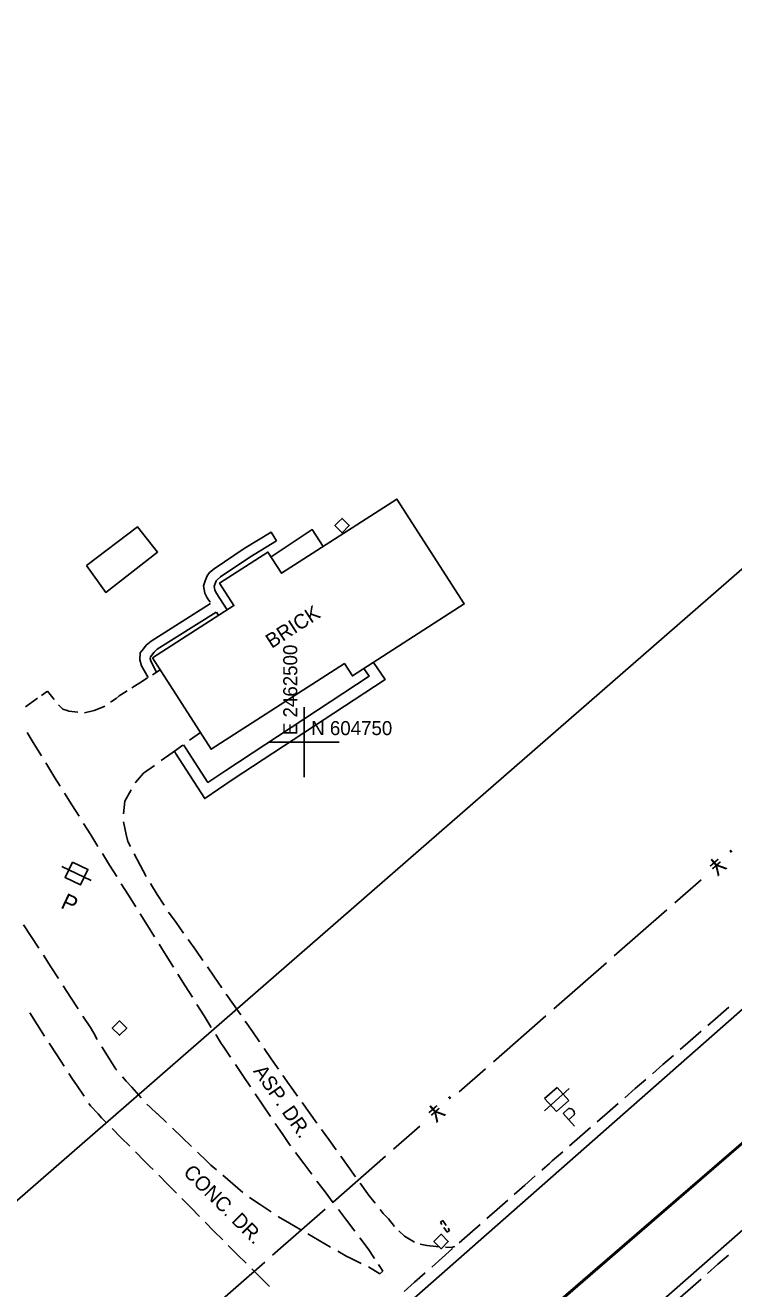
# Model space of a CAD drawing. Extents: x 2443269 to 2494951, y 591171 to 622130.
# Drawn here: x 2462420.2 to 2462622.9, y 604593.6 to 604955.1 of the extents above; entities that cross this region are included whole.
import ezdxf

# ---------------------------------------------------------------- set-up
doc = ezdxf.new("R2010")
doc.units = 0
for name, color, linetype in [('SURVEY - CONTROL - Grid', 7, 'Continuous'), ('SURVEY - CONTROL - Grid Text', 7, 'Continuous'), ('SURVEY - DRAINAGE - Area Shapes', 7, 'Continuous'), ('SURVEY - DRAINAGE - Bridges', 7, 'Continuous'), ('SURVEY - NON-TRANSPORTATION - Buildings', 7, 'Continuous'), ('SURVEY - NON-TRANSPORTATION - Buildings Text', 7, 'Continuous'), ('SURVEY - NON-TRANSPORTATION - Features', 7, 'Continuous'), ('SURVEY - PROPERTY - ROW Lines', 7, 'Continuous'), ('SURVEY - TRANSPORTATION - Features', 7, 'Continuous'), ('SURVEY - TRANSPORTATION - Features Text', 7, 'Continuous'), ('SURVEY - TRANSPORTATION - Roads', 7, 'Continuous'), ('SURVEY - UTILITIES - Cable (Underground) with Text', 7, 'Continuous'), ('SURVEY - UTILITIES - Poles and Miscellaneous with Text', 7, 'Continuous'), ('SURVEY - UTILITIES - Sanitary Sewer with Text', 7, 'Continuous')]:
    doc.layers.add(name, color=color, linetype=linetype)

# ---------------------------------------------------------------- blocks, each defined once
blk = doc.blocks.new('xpp')
at = {"layer": 'SURVEY - UTILITIES - Cable (Underground) with Text'}
for p, q in [((-4.75, 0), (4.75, 0)), ((-2.395, 2.598), (2.395, 2.598)), ((-2.395, -2.436), (-2.395, 2.598)), ((2.395, 2.598), (2.395, 2.598)), ((2.395, 2.598), (2.395, -2.436)), ((2.395, -2.436), (-2.395, -2.436)), ((-2.395, -2.436), (-2.395, -2.436)), ((2.395, -2.436), (2.395, -2.436)), ((-1.339, -8.932), (-1.339, -4.141)), ((-1.339, -4.141), (-1.339, -4.141)), ((-1.339, -4.141), (0.771, -4.141)), ((0.771, -6.496), (-1.339, -6.496)), ((1.062, -4.351), (0.771, -4.141)), ((0.771, -6.496), (1.062, -6.285)), ((1.286, -4.632), (1.062, -4.351)), ((1.062, -4.351), (1.062, -4.351)), ((1.062, -6.285), (1.286, -6.004)), ((1.062, -6.285), (1.062, -6.285)), ((1.427, -4.962), (1.286, -4.632)), ((1.286, -4.632), (1.286, -4.632)), ((1.286, -6.004), (1.427, -5.674)), ((1.286, -6.004), (1.286, -6.004)), ((1.475, -5.318), (1.427, -4.962)), ((1.427, -4.962), (1.427, -4.962)), ((1.427, -5.674), (1.475, -5.318)), ((1.427, -5.674), (1.427, -5.674)), ((1.475, -5.318), (1.475, -5.318))]:
    blk.add_line(p, q, dxfattribs=at)

msp = doc.modelspace()

# ---------------------------------------------------------------- linework, layer by layer
at = {"layer": 'SURVEY - CONTROL - Grid'}
for p, q in [((2462500, 604740), (2462500, 604760)), ((2462490, 604750), (2462510, 604750)), ((2462522.915, 604597.393), (2462522.915, 604597.393))]:
    msp.add_line(p, q, dxfattribs=at)
at = {"layer": 'SURVEY - DRAINAGE - Area Shapes'}
for points in [[(2461699.802, 604946.811), (2461948.759, 605058.451), (2462209.695, 605140.681), (2462347.245, 605149.404), (2462473.247, 605118.739), (2462639.239, 604980.206), (2462813.204, 604824.031), (2462826.669, 604809.207), (2462512.785, 604538.294), (2462060.635, 604143.095), (2461848.299, 603959.822)], [(2461699.802, 604946.811), (2461948.759, 605058.451), (2462209.695, 605140.681), (2462347.245, 605149.404), (2462473.247, 605118.739), (2462639.239, 604980.206), (2462813.204, 604824.031), (2462826.669, 604809.207), (2462404.086, 604443.772), (2462278.014, 604331.283), (2462060.635, 604143.095), (2461831.285, 603941.863)]]:
    msp.add_lwpolyline(points, dxfattribs=at)
at = {"layer": 'SURVEY - DRAINAGE - Bridges'}
for p, q in [((2462539.71, 604613.109), (2462538.995, 604612.643)), ((2462538.995, 604612.643), (2462539.418, 604611.993)), ((2462539.71, 604613.109), (2462540.599, 604611.744)), ((2462539.973, 604611.14), (2462540.862, 604609.776)), ((2462541.577, 604610.241), (2462540.862, 604609.776)), ((2462540.862, 604609.776), (2462540.862, 604609.776)), ((2462541.154, 604610.891), (2462541.577, 604610.241))]:
    msp.add_line(p, q, dxfattribs=at)
at = {"layer": 'SURVEY - NON-TRANSPORTATION - Buildings'}
msp.add_lwpolyline([(2462456.574, 604774.07), (2462479.907, 604789.08), (2462475.786, 604795.487), (2462489.615, 604804.381), (2462493.523, 604798.309), (2462526.515, 604819.529), (2462545.809, 604789.532), (2462513.772, 604768.929), (2462511.492, 604772.475), (2462473.368, 604747.958)], close=True, dxfattribs=at)
at = {"layer": 'SURVEY - NON-TRANSPORTATION - Features'}
msp.add_line((2462475.485, 604786.235), (2462474.881, 604787.18), dxfattribs=at)
for points in [[(2462509.807, 604812.984), (2462510.838, 604814.015), (2462512.9, 604811.953), (2462510.838, 604809.89), (2462508.775, 604811.953)], [(2462437.696, 604800.484), (2462452.25, 604811.626), (2462458.057, 604804.349), (2462443.214, 604792.833)], [(2462446.122, 604669.211), (2462447.154, 604670.242), (2462449.216, 604668.18), (2462447.154, 604666.118), (2462445.091, 604668.18)], [(2462538.143, 604608.148), (2462539.174, 604609.179), (2462541.237, 604607.117), (2462539.174, 604605.055), (2462537.112, 604607.117)]]:
    msp.add_lwpolyline(points, close=True, dxfattribs=at)
for points in [[(2462473.076, 604789.995), (2462472.253, 604791.284), (2462471.603, 604792.62), (2462471.151, 604794.713), (2462471.643, 604796.13), (2462472.227, 604797.551), (2462472.903, 604798.492), (2462474.244, 604799.618), (2462482.857, 604805.412), (2462490.504, 604810.077), (2462492.04, 604807.554)], [(2462505.452, 604805.979), (2462502.286, 604810.802), (2462490.517, 604802.981)], [(2462477.971, 604787.833), (2462474.832, 604792.731), (2462474.415, 604793.591), (2462474.212, 604794.526), (2462474.405, 604795.084), (2462474.825, 604796.11), (2462475.084, 604796.468), (2462476.023, 604797.255), (2462484.451, 604802.925), (2462492.04, 604807.554)], [(2462455.36, 604768.483), (2462453.428, 604771.832), (2462452.972, 604773.548), (2462453.09, 604775.54), (2462454.051, 604776.668), (2462454.822, 604777.705), (2462456.164, 604778.925), (2462473.185, 604789.66)], [(2462457.719, 604769.972), (2462456.187, 604772.948), (2462455.947, 604773.847), (2462455.98, 604774.378), (2462456.361, 604774.828), (2462457.02, 604775.714), (2462457.958, 604776.567), (2462474.76, 604787.164)], [(2462519.812, 604772.813), (2462523.181, 604767.944), (2462479.376, 604739.178), (2462471.531, 604733.85), (2462463.136, 604746.793), (2462462.863, 604747.436)], [(2462517.049, 604771.038), (2462518.572, 604768.84), (2462477.555, 604741.908), (2462472.46, 604738.447), (2462466.013, 604748.384), (2462465.416, 604749.257)]]:
    msp.add_lwpolyline(points, dxfattribs=at)
at = {"layer": 'SURVEY - PROPERTY - ROW Lines'}
msp.add_line((2462832.634, 604980.177), (2461653.501, 603953.054), dxfattribs=at)
at = {"layer": 'SURVEY - TRANSPORTATION - Features'}
for p, q in [((2462456.548, 604769.233), (2462458.779, 604770.641)), ((2462458.779, 604770.641), (2462458.779, 604770.641)), ((2462450.691, 604765.535), (2462452.922, 604766.944)), ((2462452.922, 604766.944), (2462455.153, 604768.352)), ((2462424.818, 604763.355), (2462426.567, 604764.601)), ((2462426.567, 604764.601), (2462426.567, 604764.601)), ((2462426.567, 604764.601), (2462428.472, 604762.169)), ((2462446.203, 604762.495), (2462447.066, 604763.246)), ((2462447.066, 604763.246), (2462449.297, 604764.655)), ((2462447.066, 604763.246), (2462447.066, 604763.246)), ((2462420.224, 604760.082), (2462421.974, 604761.329)), ((2462421.974, 604761.329), (2462423.724, 604762.575)), ((2462429.68, 604760.664), (2462430.974, 604759.431)), ((2462430.974, 604759.431), (2462432.204, 604759.004)), ((2462440.145, 604759.146), (2462442.758, 604760.159)), ((2462442.758, 604760.159), (2462442.993, 604760.325)), ((2462444.567, 604761.444), (2462444.865, 604761.655)), ((2462444.865, 604761.655), (2462446.203, 604762.495)), ((2462432.204, 604759.004), (2462432.676, 604758.84)), ((2462432.676, 604758.84), (2462435.248, 604758.533)), ((2462437.162, 604758.35), (2462439.897, 604759.05)), ((2462439.897, 604759.05), (2462440.145, 604759.146)), ((2462422.745, 604749.399), (2462420.706, 604752.702)), ((2462470.294, 604752.738), (2462467.198, 604750.529)), ((2462424.783, 604746.097), (2462422.745, 604749.399)), ((2462465.264, 604749.149), (2462462.168, 604746.941)), ((2462462.168, 604746.941), (2462459.072, 604744.732)), ((2462428.095, 604740.73), (2462426.057, 604744.032)), ((2462454.041, 604741.143), (2462451.731, 604738.417)), ((2462457.137, 604743.352), (2462454.041, 604741.143)), ((2462454.041, 604741.143), (2462454.041, 604741.143)), ((2462428.67, 604739.798), (2462428.095, 604740.73)), ((2462430.149, 604737.437), (2462428.67, 604739.798)), ((2462451.731, 604738.417), (2462451.67, 604738.313)), ((2462433.497, 604732.092), (2462431.437, 604735.381)), ((2462450.503, 604736.321), (2462448.636, 604733.134)), ((2462435.557, 604728.803), (2462433.497, 604732.092)), ((2462448.634, 604733.132), (2462448.264, 604729.459)), ((2462448.636, 604733.134), (2462448.634, 604733.132)), ((2462438.904, 604723.458), (2462436.844, 604726.747)), ((2462448.249, 604727.176), (2462449.08, 604723.576)), ((2462440.964, 604720.169), (2462438.904, 604723.458)), ((2462449.08, 604723.576), (2462449.55, 604721.54)), ((2462449.55, 604721.54), (2462450.289, 604720.116)), ((2462444.312, 604714.824), (2462442.252, 604718.114)), ((2462451.352, 604718.067), (2462453.054, 604714.788)), ((2462446.372, 604711.535), (2462444.312, 604714.824)), ((2462453.054, 604714.788), (2462454.755, 604711.51)), ((2462449.719, 604706.19), (2462447.659, 604709.48)), ((2462455.972, 604709.549), (2462457.944, 604706.425)), ((2462451.779, 604702.901), (2462449.719, 604706.19)), ((2462457.944, 604706.425), (2462459.915, 604703.301)), ((2462461.176, 604701.368), (2462463.324, 604698.363)), ((2462455.126, 604697.557), (2462453.066, 604700.846)), ((2462463.324, 604698.363), (2462465.472, 604695.358)), ((2462419.715, 604697.677), (2462421.867, 604694.37)), ((2462421.867, 604694.37), (2462424.018, 604691.062)), ((2462457.186, 604694.267), (2462455.126, 604697.557)), ((2462460.534, 604688.923), (2462458.474, 604692.212)), ((2462466.814, 604693.479), (2462468.962, 604690.474)), ((2462425.363, 604688.995), (2462427.514, 604685.687)), ((2462462.594, 604685.634), (2462460.534, 604688.923)), ((2462468.962, 604690.474), (2462468.962, 604690.474)), ((2462468.962, 604690.474), (2462471.02, 604687.514)), ((2462427.514, 604685.687), (2462429.666, 604682.38)), ((2462465.941, 604680.289), (2462463.881, 604683.578)), ((2462472.306, 604685.664), (2462474.364, 604682.704)), ((2462431.011, 604680.312), (2462433.162, 604677.005)), ((2462468.001, 604677), (2462465.941, 604680.289)), ((2462474.364, 604682.704), (2462476.422, 604679.743)), ((2462433.162, 604677.005), (2462435.314, 604673.697)), ((2462477.708, 604677.893), (2462479.766, 604674.933)), ((2462423.6, 604669.212), (2462421.468, 604672.515)), ((2462471.349, 604671.655), (2462469.289, 604674.944)), ((2462479.766, 604674.933), (2462481.824, 604671.973)), ((2462618.484, 604671.527), (2462621.5, 604674.151)), ((2462425.731, 604665.909), (2462423.6, 604669.212)), ((2462436.659, 604671.63), (2462438.81, 604668.323)), ((2462473.409, 604668.366), (2462471.349, 604671.655)), ((2462483.11, 604670.123), (2462485.168, 604667.162)), ((2462615.468, 604668.902), (2462618.484, 604671.527)), ((2462438.81, 604668.323), (2462439.829, 604666.757)), ((2462439.829, 604666.757), (2462440.799, 604664.919)), ((2462476.265, 604663.804), (2462474.696, 604666.31)), ((2462485.168, 604667.162), (2462487.226, 604664.202)), ((2462610.567, 604664.636), (2462613.583, 604667.261)), ((2462429.195, 604660.541), (2462427.063, 604663.844)), ((2462442.089, 604662.819), (2462444.212, 604659.493)), ((2462476.782, 604663.038), (2462476.265, 604663.804)), ((2462478.951, 604659.819), (2462476.782, 604663.038)), ((2462488.513, 604662.352), (2462490.57, 604659.392)), ((2462607.551, 604662.011), (2462610.567, 604664.636)), ((2462431.326, 604657.237), (2462429.195, 604660.541)), ((2462444.212, 604659.493), (2462444.212, 604659.493)), ((2462444.212, 604659.493), (2462446.079, 604656.436)), ((2462490.57, 604659.392), (2462492.628, 604656.432)), ((2462602.65, 604657.746), (2462605.666, 604660.371)), ((2462433.713, 604653.539), (2462432.658, 604655.173)), ((2462446.079, 604656.436), (2462446.351, 604656.122)), ((2462482.475, 604654.59), (2462480.306, 604657.808)), ((2462484.644, 604651.371), (2462482.475, 604654.59)), ((2462493.915, 604654.581), (2462495.698, 604652.016)), ((2462599.634, 604655.121), (2462602.65, 604657.746)), ((2462434.842, 604651.905), (2462433.713, 604653.539)), ((2462437.077, 604648.671), (2462434.842, 604651.905)), ((2462447.991, 604654.237), (2462449.077, 604652.987)), ((2462449.077, 604652.987), (2462450.637, 604651.24)), ((2462450.637, 604651.24), (2462453.298, 604648.257)), ((2462495.698, 604652.016), (2462495.979, 604651.626)), ((2462495.979, 604651.626), (2462498.083, 604648.698)), ((2462591.717, 604648.23), (2462594.733, 604650.855)), ((2462594.733, 604650.855), (2462597.749, 604653.48)), ((2462488.169, 604646.141), (2462486, 604649.36)), ((2462438.851, 604645.891), (2462438.407, 604646.605)), ((2462441.013, 604643.683), (2462438.851, 604645.891)), ((2462441.948, 604642.535), (2462441.013, 604643.683)), ((2462454.969, 604646.399), (2462455.928, 604645.507)), ((2462455.928, 604645.507), (2462457.903, 604643.683)), ((2462457.903, 604643.778), (2462460.616, 604641.174)), ((2462457.903, 604643.683), (2462457.903, 604643.683)), ((2462490.338, 604642.923), (2462488.169, 604646.141)), ((2462499.399, 604646.869), (2462501.504, 604643.942)), ((2462501.504, 604643.942), (2462503.608, 604641.015)), ((2462583.799, 604641.34), (2462586.815, 604643.965)), ((2462586.815, 604643.965), (2462589.831, 604646.59)), ((2462443.428, 604641.025), (2462441.948, 604642.535)), ((2462493.862, 604637.693), (2462491.693, 604640.912)), ((2462447.56, 604636.895), (2462445.016, 604639.436)), ((2462450.104, 604634.355), (2462447.56, 604636.895)), ((2462462.312, 604639.547), (2462465.026, 604636.943)), ((2462465.026, 604636.943), (2462467.74, 604634.339)), ((2462495.793, 604634.828), (2462493.862, 604637.693)), ((2462504.924, 604639.185), (2462507.028, 604636.258)), ((2462575.882, 604634.449), (2462578.898, 604637.074)), ((2462578.898, 604637.074), (2462581.914, 604639.699)), ((2462454.237, 604630.227), (2462451.693, 604632.767)), ((2462469.436, 604632.711), (2462472.15, 604630.107)), ((2462496.049, 604634.488), (2462495.793, 604634.828)), ((2462507.028, 604636.258), (2462509.133, 604633.331)), ((2462570.981, 604630.184), (2462573.997, 604632.809)), ((2462455.849, 604628.617), (2462454.237, 604630.227)), ((2462472.15, 604630.107), (2462473.316, 604628.988)), ((2462499.848, 604629.454), (2462497.51, 604632.552)), ((2462502.186, 604626.356), (2462499.848, 604629.454)), ((2462510.448, 604631.501), (2462512.553, 604628.574)), ((2462567.977, 604627.546), (2462570.173, 604629.48)), ((2462570.173, 604629.48), (2462570.981, 604630.184)), ((2462456.776, 604627.681), (2462455.849, 604628.617)), ((2462460.886, 604623.53), (2462458.357, 604626.085)), ((2462473.316, 604628.988), (2462474.947, 604627.596)), ((2462476.735, 604626.07), (2462479.596, 604623.628)), ((2462512.553, 604628.574), (2462514.658, 604625.647)), ((2462563.101, 604623.251), (2462566.102, 604625.894)), ((2462463.415, 604620.976), (2462460.886, 604623.53)), ((2462479.596, 604623.628), (2462482.457, 604621.187)), ((2462505.984, 604621.322), (2462503.647, 604624.42)), ((2462515.973, 604623.818), (2462518.078, 604620.89)), ((2462560.101, 604620.608), (2462563.101, 604623.251)), ((2462467.526, 604616.825), (2462464.996, 604619.379)), ((2462484.309, 604619.745), (2462487.44, 604617.662)), ((2462508.322, 604618.224), (2462505.984, 604621.322)), ((2462518.078, 604620.89), (2462518.332, 604620.537)), ((2462518.332, 604620.537), (2462520.317, 604618.065)), ((2462555.225, 604616.314), (2462558.226, 604618.956)), ((2462470.055, 604614.27), (2462467.526, 604616.825)), ((2462487.44, 604617.662), (2462490.571, 604615.578)), ((2462512.121, 604613.19), (2462509.783, 604616.288)), ((2462521.728, 604616.308), (2462522.64, 604615.172)), ((2462522.64, 604615.172), (2462523.204, 604614.595)), ((2462523.204, 604614.595), (2462524.143, 604613.637)), ((2462552.225, 604613.671), (2462555.225, 604616.314)), ((2462474.166, 604610.119), (2462471.636, 604612.674)), ((2462492.528, 604614.276), (2462492.689, 604614.169)), ((2462492.689, 604614.169), (2462495.773, 604612.375)), ((2462495.773, 604612.375), (2462499.025, 604610.485)), ((2462514.458, 604610.092), (2462512.121, 604613.19)), ((2462524.143, 604613.637), (2462525.839, 604611.43)), ((2462547.35, 604609.376), (2462550.35, 604612.019)), ((2462476.695, 604607.565), (2462474.166, 604610.119)), ((2462501.057, 604609.303), (2462504.308, 604607.413)), ((2462504.308, 604607.413), (2462507.56, 604605.522)), ((2462518.257, 604605.058), (2462515.919, 604608.156)), ((2462527.05, 604610.189), (2462528.742, 604608.653)), ((2462528.742, 604608.653), (2462529.169, 604608.394)), ((2462529.169, 604608.394), (2462531.546, 604606.946)), ((2462544.349, 604606.733), (2462547.35, 604609.376)), ((2462480.081, 604604.146), (2462478.276, 604605.968)), ((2462480.813, 604603.421), (2462480.081, 604604.146)), ((2462509.592, 604604.341), (2462512.168, 604602.843)), ((2462520.137, 604602.278), (2462518.257, 604605.058)), ((2462518.257, 604605.058), (2462518.257, 604605.058)), ((2462533.155, 604606.364), (2462535.078, 604606.022)), ((2462535.078, 604606.022), (2462535.903, 604605.924)), ((2462535.903, 604605.924), (2462538.667, 604605.593)), ((2462539.474, 604602.438), (2462542.474, 604605.081)), ((2462540.401, 604605.455), (2462542.095, 604605.376)), ((2462542.095, 604605.376), (2462543.142, 604605.671)), ((2462543.142, 604605.671), (2462543.142, 604605.671)), ((2462483.368, 604600.892), (2462480.813, 604603.421)), ((2462512.168, 604602.843), (2462512.871, 604602.503)), ((2462512.871, 604602.503), (2462516.256, 604600.864)), ((2462521.807, 604599.703), (2462521.288, 604600.524)), ((2462536.473, 604599.796), (2462539.474, 604602.438)), ((2462618.395, 604600.605), (2462615.415, 604597.979)), ((2462621.376, 604603.231), (2462618.395, 604600.605)), ((2462487.52, 604596.783), (2462484.965, 604599.312)), ((2462490.075, 604594.254), (2462487.52, 604596.783)), ((2462518.372, 604599.839), (2462518.388, 604599.831)), ((2462518.388, 604599.831), (2462521.593, 604597.899)), ((2462521.593, 604597.899), (2462522.46, 604598.653)), ((2462521.593, 604597.899), (2462521.593, 604597.899)), ((2462522.46, 604598.653), (2462521.807, 604599.703)), ((2462531.598, 604595.501), (2462534.598, 604598.144)), ((2462528.598, 604592.858), (2462531.598, 604595.501)), ((2462610.572, 604593.712), (2462607.591, 604591.086)), ((2462613.552, 604596.337), (2462610.572, 604593.712))]:
    msp.add_line(p, q, dxfattribs=at)
at = {"layer": 'SURVEY - TRANSPORTATION - Roads'}
for points in [[(2461704.19, 603879.846), (2461710.507, 603878.998), (2461720.352, 603882.211), (2461736.892, 603894.969), (2461821.567, 603969.133), (2462007.389, 604131.918), (2462224.619, 604322.385), (2462361.423, 604442.233), (2462529.864, 604589.484), (2462660.404, 604704.382), (2462778.493, 604807.784)], [(2462812.347, 604774.503), (2462577.786, 604568.609), (2462133.041, 604178.976), (2462140.797, 604171.85)]]:
    msp.add_lwpolyline(points, dxfattribs=at)
at = {"layer": 'SURVEY - UTILITIES - Poles and Miscellaneous with Text'}
for q in [(2462430.605, 604714.407), (2462439.065, 604710.426)]:
    msp.add_line((2462434.835, 604712.416), q, dxfattribs=at)
msp.add_lwpolyline([(2462433.656, 604715.691), (2462438.109, 604713.595), (2462436.014, 604709.142), (2462431.561, 604711.238)], close=True, dxfattribs=at)
at = {"layer": 'SURVEY - UTILITIES - Sanitary Sewer with Text'}
for p, q in [((2462613.549, 604710.61), (2462606.028, 604704.019)), ((2462603.772, 604702.042), (2462588.731, 604688.86)), ((2462586.475, 604686.882), (2462578.954, 604680.291)), ((2462578.954, 604680.291), (2462571.434, 604673.7)), ((2462569.177, 604671.723), (2462554.136, 604658.541)), ((2462551.88, 604656.564), (2462544.359, 604649.973)), ((2462533.079, 604640.086), (2462525.558, 604633.495)), ((2462523.302, 604631.518), (2462508.261, 604618.336)), ((2462506.004, 604616.359), (2462498.484, 604609.768)), ((2462498.484, 604609.768), (2462490.963, 604603.177)), ((2462488.707, 604601.2), (2462473.666, 604588.018))]:
    msp.add_line(p, q, dxfattribs=at)

# ---------------------------------------------------------------- block references
at = {"layer": 'SURVEY - UTILITIES - Poles and Miscellaneous with Text', "rotation": 42.029325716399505}
msp.add_blockref('xpp', (2462572.312, 604647.692), dxfattribs=at)

# ---------------------------------------------------------------- texts
at = {"layer": 'SURVEY - CONTROL - Grid Text'}
msp.add_text('E 2462500', height=4, rotation=90, dxfattribs=at).set_placement((2462498, 604752))
msp.add_text('N 604750', height=4, dxfattribs=at).set_placement((2462502, 604752))
at = {"layer": 'SURVEY - NON-TRANSPORTATION - Buildings Text'}
msp.add_text('BRICK', height=4.166, rotation=32.74556, dxfattribs=at).set_placement((2462490.679, 604776.665))
at = {"layer": 'SURVEY - TRANSPORTATION - Features Text'}
for s, rotation, p in [('ASP. DR.', 304.80658, (2462485.281, 604655.841)), ('CONC. DR.', 315.03861, (2462465.144, 604626.61))]:
    msp.add_text(s, height=4.166, rotation=rotation, dxfattribs=at).set_placement(p)
at = {"layer": 'SURVEY - UTILITIES - Poles and Miscellaneous with Text'}
msp.add_text('P', height=4.675, rotation=334.79999, dxfattribs=at).set_placement((2462430.026, 604702.714))
at = {"layer": 'SURVEY - UTILITIES - Sanitary Sewer with Text'}
for s, p in [('¥', (2462617.855, 604717.708)), ('·', (2462621.615, 604721.003)), ('·', (2462541.145, 604650.48)), ('¥', (2462537.385, 604647.184))]:
    msp.add_text(s, height=5, rotation=221.231, dxfattribs=at).set_placement(p)

doc.saveas('drawing.dxf')
